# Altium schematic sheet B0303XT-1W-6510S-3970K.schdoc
size 277 x 190 mm; Device: default297x210; Symbol: default297x210; Name: default297x210; Date: 2026.02.28; Rev: V1.0; Size: "A4"; Id: /; File: B0303XT-1W-6510S-3970K; Sheet: /
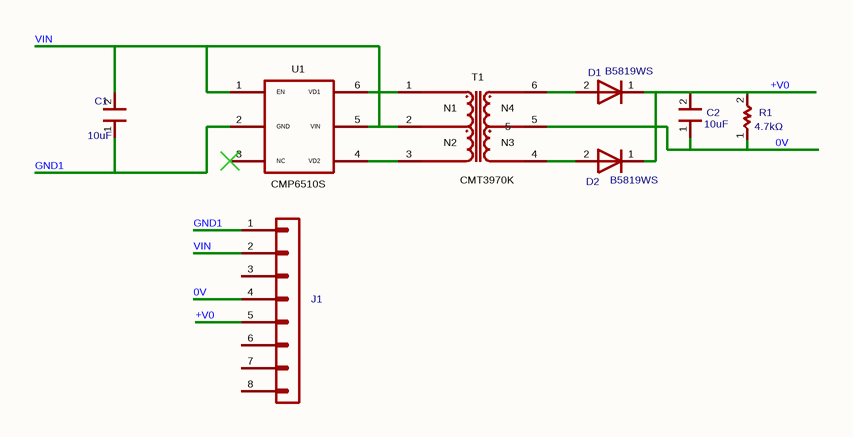
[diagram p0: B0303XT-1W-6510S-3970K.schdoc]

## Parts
C1  10uF  [MYLibrary:C0603]
C2  10uF  [MYLibrary:C0603]
D1  B5819WS  [MYLibrary:SOD-323]
D2  B5819WS  [MYLibrary:SOD-323]
J1  Connector_Generic_Conn_01x08  [MYLibrary:F0505XT-8PIN]  (value not drawn)
R1  4.7kΩ  [MYLibrary:R0603]
T1  (no value)  [CMT3970K]
U1  (no value)  [CMP6510S]

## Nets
0V: C2.1 J1.4(Pin_4) R1.1 T1.5
+V0: C2.2 D1.1(K) D2.1(K) J1.5(Pin_5) R1.2
GND1: C1.1 J1.1(Pin_1) U1.2(GND)
VIN: C1.2 J1.2(Pin_2) T1.2 U1.1(EN) U1.5(VIN)
NetD1_2: D1.2(A) T1.6
NetD2_2: D2.2(A) T1.4
NetT1_1: T1.1 U1.6(VD1)
NetT1_3: T1.3 U1.4(VD2)

Not connected (* = marked no-connect by the designer): J1 3(Pin_3) 6(Pin_6) 7(Pin_7) 8(Pin_8); U1 3(NC)*

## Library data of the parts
C1 C2 = 0603X106K100NT: 容值:10uF;精度:±10%;额定电压:10V;温度系数:X5R;; Manufacturer: FH(风华); Symbol: Coileasy library_C; Add into BOM: yes; 3D Model: ac125912035d415993ca9572d50418b1; 3D Model Transform: 62.992,31.496,0,0,0,0,0,0,0; Tolerance: ±10%; Voltage Rating: 10V; Temperature Coefficient: X5R; ki_keywords: cap capacitor; ki_fp_filters: C_*; ModelName: C0603_L1.6-W0.8-H0.8
D1 D2 = B5819WS_C64886: 二极管配置:独立式;正向压降(Vf):900mV@3A;直流反向耐压(Vr):40V;整流电流:1A;; Manufacturer: MDD(辰达半导体); Symbol: Coileasy library_D; Add into BOM: yes; 3D Model: 7459fe65e23146c0a8d836e46a0add72; 3D Model Transform: 104.3305,51.181,0,0,0,0,0,0,0; Diode Configuration: 独立式; Voltage - DC Reverse(Vr): 40V; Current - Rectified: 1A; Reverse Leakage Current (Ir): 1mA@40V; Operating Junction Temperature Range: -55℃~+125℃; Non-Repetitive Peak Forward Surge Current: 25A; Value: D; ki_keywords: diode; ki_fp_filters: TO-???* *_Diode_* *SingleDiode* D_*; ModelName: SOD-323_L1.8-W1.3-LS2.5-RD
J1 = Connector_Generic_Conn_01x08: Generic connector, single row, 01x08, script generated (kicad-library-utils/schlib/autogen/connector/); ki_fp_filters: Connector*:*_1x??_*; UniqueId: 9f49826860c2c79d; AddInBom: yes
R1 = RC0603FR-074K7L: 电阻类型:厚膜电阻;阻值:4.7kΩ;精度:±1%;功率:100mW;工作电压:75V;温度系数:±100ppm/℃;; Manufacturer: YAGEO(国巨); Symbol: Coileasy library_R; Add into BOM: yes; 3D Model: fc143cca1e79419f9cd78b61e9279f08; 3D Model Transform: 31.8897,63.7794,0,90,0,0,0,0,0; Tolerance: ±1%; Power(Watts): 100mW; Voltage-Supply(Max): 75V; ki_keywords: R res resistor; ki_fp_filters: R_*; ModelName: R0603
T1 = CMT3970K: AddInBom: yes
U1 = CMP6510S: AddInBom: yes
